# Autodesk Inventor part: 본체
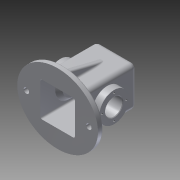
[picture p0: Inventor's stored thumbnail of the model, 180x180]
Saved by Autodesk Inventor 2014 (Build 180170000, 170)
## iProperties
Created: 2017-07
Part Number: 본체
Material: Aluminum 6061
Document SubType Name: Modeling
Designer: user
Density: 2.71 g/cm^3
Appearance: Aluminum - Flat
Mass: 892.454 g
Surface Area: 987.915 cm^2
Volume: 329.319 cm^3
Author: user
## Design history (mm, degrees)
sketch "Sketch1" dims "d0" = 65, "d1" = 75
  geometry: 2 further points; 1 other entity
  constraints: 1 coincident, 2 other
extrude "Extrusion1" new body sketch "Sketch1" distance "d2" = 10; taper "d3" = 0 deg
sketch "Sketch2"
  geometry: L1 (-37, -37)-(37, -37); L2 (37, -37)-(37, 37); L3 (37, 37)-(-37, 37); L4 (-37, 37)-(-37, -37); L5 (-37, -37)-(37, 37); L6 (37, -37)-(-37, 37); 1 further point; 1 other entity
  constraints: 12 end point, 2 midpoint, 1 other
extrude "Extrusion2" join sketch "Sketch2" distance "d4" = 100; taper "d5" = 0 deg
sketch "Sketch3"
  geometry: L1 (-20, -20)-(20, -20); L2 (20, -20)-(20, 20); L3 (20, 20)-(-20, 20); L4 (-20, 20)-(-20, -20); L5 (-20, -20)-(20, 20); L6 (20, -20)-(-20, 20); 1 further point
  constraints: 12 end point, 2 midpoint
extrude "Extrusion3" join sketch "Sketch3" distance "d6" = 10; taper "d7" = -5 deg
sketch "Sketch4"
  geometry: L1 (-28, -10)-(102, -10) reference; C1 r 27.5 at (37, 45); 1 further point
  constraints: 1 centre point
  dimensions: "d8" = 55 distance from line of L1 C1.centre; "d9" = 55 diameter of C1
extrude "Extrusion4" join sketch "Sketch4" distance "d10" = 13; taper "d11" = 0 deg
sketch "Sketch5"
  geometry: L1 (32, 32)-(-32, 32); L2 (-32, 32)-(-32, -32); L3 (-32, -32)-(32, -32); L4 (32, -32)-(32, 32); L5 (32, 32)-(-32, -32); L6 (-32, 32)-(32, -32); 1 further point; 1 other entity
  constraints: 12 end point, 2 midpoint, 1 other
  dimensions: "d12" = 64 distance of L2.end L3.end; "d13" = 64 distance of L1.end L2.end
extrude "Extrusion5" cut sketch "Sketch5" distance "d14" = 105; taper "d15" = 0 deg
sketch "Sketch6"
  geometry: C1 r 14 at (0, 0); 1 further point
  constraints: 1 centre point, 1 coincident
  dimensions: "d16" = 28 diameter of C1
extrude "Extrusion6" cut sketch "Sketch6" distance "d17" = 4; taper "d18" = 0 deg
sketch "Sketch7"
  geometry: C1 r 14 at (0, 0) reference; C2 r 10.5 at (0, 0)
  constraints: 1 centre point, 1 coincident
  dimensions: "d19" = 21 diameter of C2
extrude "Extrusion7" cut sketch "Sketch7" stored distance "d20" = 4; taper "d21" = 0 deg
sketch "Sketch9"
  geometry: L1 (-33, 0)-(97, 0) reference; C1 r 27.5 at (32, 55); 1 further point
  constraints: 1 centre point
  dimensions: "d22" = 55 diameter of C1; "d23" = 55 distance from line of L1 C1.centre
extrude "Extrusion8" join sketch "Sketch9" distance "d24" = 7; taper "d25" = -45 deg
sketch "Sketch11"
  geometry: C1 r 27.5 at (0, 0) reference; C2 r 16 at (0, 0); 1 further point
  constraints: 1 centre point, 1 coincident
  dimensions: "d26" = 32 diameter of C2
extrude "Extrusion9" cut sketch "Sketch11" stored distance "d27" = 7; taper "d28" = 0 deg
sketch "Sketch12"
  geometry: L1 (0, -22.5)-(0, 22.5); L2 (22.5, 0)-(-22.5, 0); A1 r 22.5 centre (0, 0) between (0, 22.5) and (0, -22.5); 2 further points
  constraints: 4 end point, 4 point on circle, 1 centre point, 1 coincident, 1 midpoint
  dimensions: "d29" = 45 diameter of A1
hole "Hole2" sketch "Sketch12" at (0, 22.5), (22.5, 0), (0, -22.5), (-22.5, 0) diameter "d37" = 3.459; stored, may be unused: countersink angle "d41" = 90 deg, drill point angle "d43" = 118 deg; dims "d38" = 8, "d39" = 4, "d40" = 2, "d42" = 10
workplane "Work Plane1"
mirror "Mirror1"
sketch "Sketch13"
  geometry: L1 (74, 0)-(74, 100) reference; L2 (56.125, 110)-(17.875, 110) reference; L3 (16.577, 82.825)-(58.056, 82.825); L4 (58.056, 82.825)-(58.056, 76.821); L5 (58.056, 76.821)-(16.577, 76.821); L6 (16.577, 76.821)-(16.577, 82.825); 2 further points
  constraints: 2 other
  dimensions: "d44" = 30 distance from line of L2 point (37, 80); "d45" = 37 distance from line of point (37, 80) L1
emboss "Emboss1" sketch "Sketch13" dims "d46" = 0.5, "d47" = 0
sketch "Sketch14"
  geometry: L1 (10, -65)-(10, 65) reference; L2 (0, 65)-(0, -65) reference; L3 (10, 55)-(82.194, 37); L4 (82.194, 37)-(10, 37); 1 further point
  constraints: 4 end point, 2 point on line
  dimensions: "d49" = 10 distance of L3.start L1.end; "d50" = 14 deg angle of L4 L3
extrude "Extrusion10" join sketch "Sketch14" stored distance "d51" = 10; taper "d52" = 0 deg
fillet "Fillet1" dims "d53" = 8
workplane "Work Plane2"
mirror "Mirror2"
fillet "Fillet2" dims "d54" = 3
fillet "Fillet3" dims "d55" = 3
fillet "Fillet4" dims "d56" = 3
fillet "Fillet5" dims "d57" = 0.5
chamfer "Chamfer1" distance "d58" = 1; stored, may be unused: second distance "d59" = 2, angle "d60" = 45 deg
fillet "Fillet6" dims "d61" = 0.5
fillet "Fillet7" dims "d62" = 3
sketch "Sketch15"
  geometry: L1 (-58, 0)-(58, 0); C1 r 5 at (-58, 0); C2 r 5 at (58, 0); 1 further point; 1 other entity
  constraints: 2 centre point, 2 end point, 1 other
  dimensions: "d63" = 58 distance of point (0, 0) L1.end; "d64" = 58 distance of L1.start point (0, 0)
extrude "Extrusion11" cut sketch "Sketch15" distance "d65" = 10; taper "d66" = 0 deg
fillet "Fillet8" dims "d67" = 3
body "Solid1"
node "Projected Loop1"
